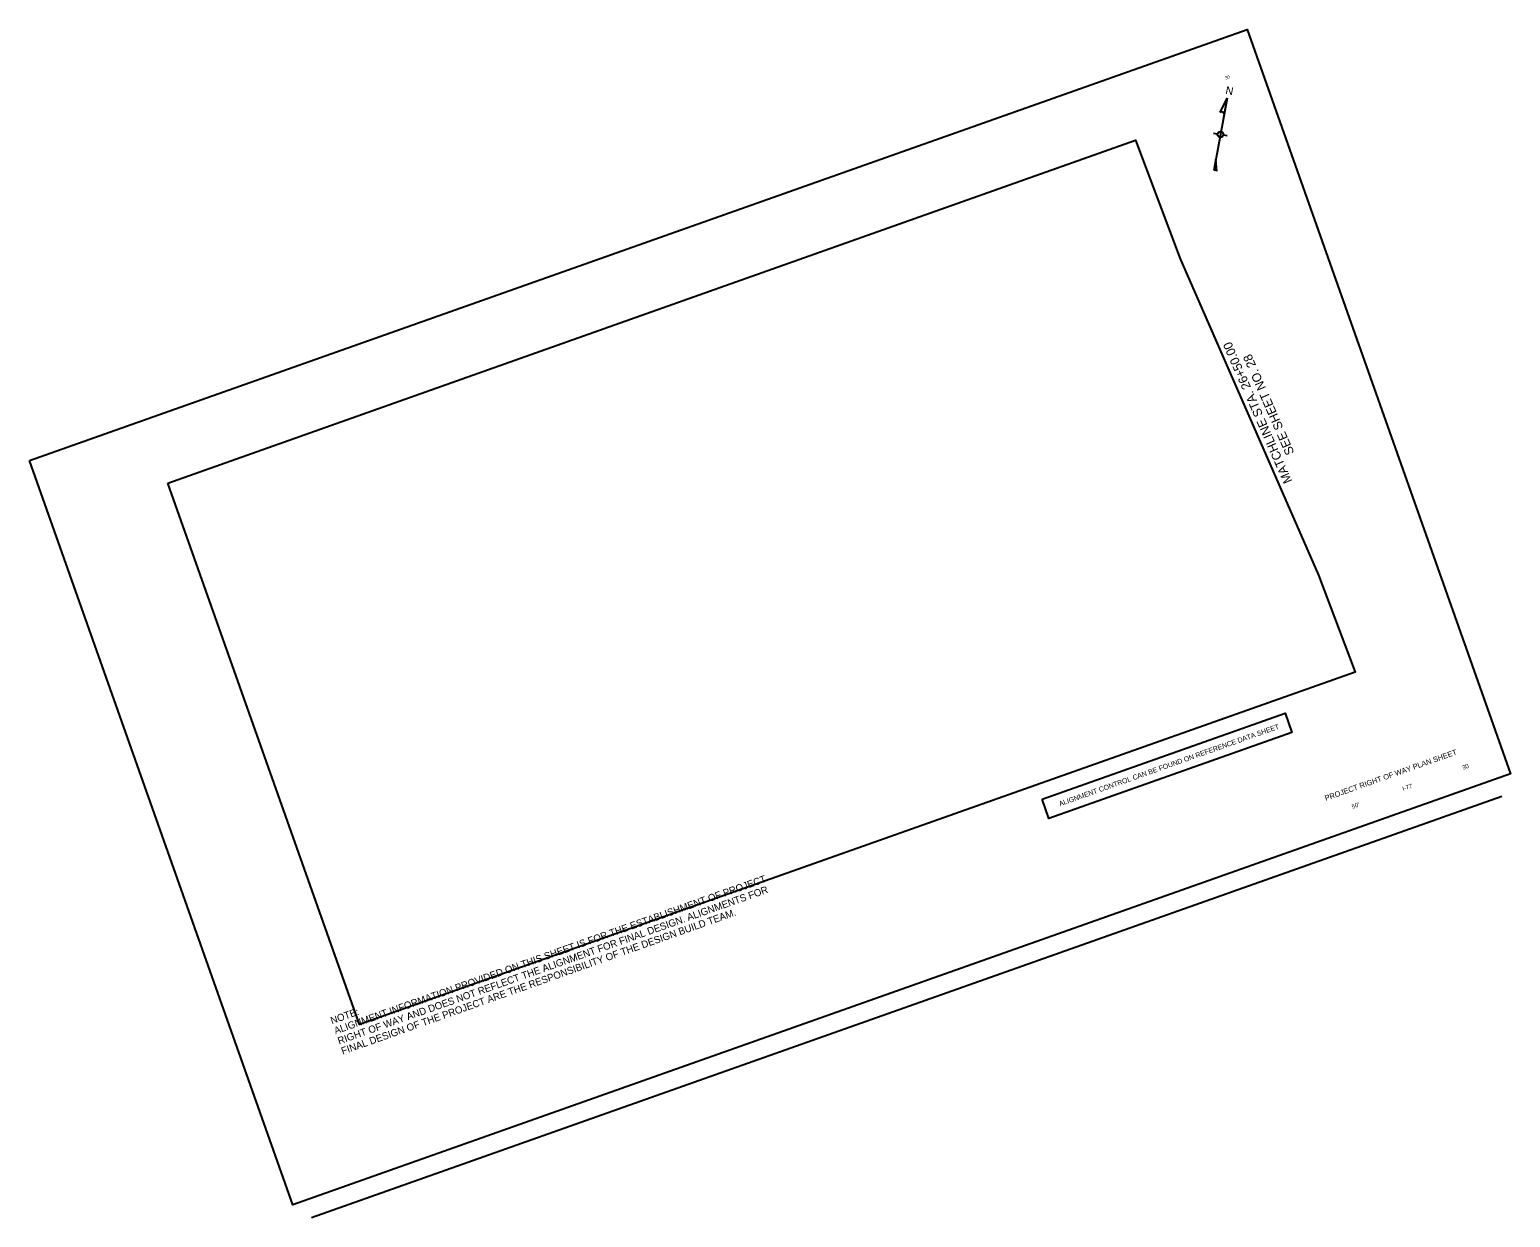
# Model space of a CAD drawing. Extents: x 2003337 to 2005401, y 1135705 to 1137360.
import ezdxf

# ---------------------------------------------------------------- set-up
doc = ezdxf.new("R2010")
doc.units = 0
for name, color, linetype in [('North Arrow', 7, 'Continuous'), ('RD_SHT_IplotShp', 7, 'Continuous'), ('RD_SHT_MatchLine', 7, 'Continuous'), ('RD_SHT_Misc1', 7, 'Continuous'), ('RD_SHT_ShtClip', 7, 'Continuous'), ('RD_SHT_TX', 7, 'Continuous')]:
    doc.layers.add(name, color=color, linetype=linetype)

msp = doc.modelspace()

# ---------------------------------------------------------------- linework, layer by layer
at = {"layer": 'North Arrow'}
for p, q in [((2005006.1, 1137264.4), (2004987.3, 1137163.9)), ((2004996.4, 1137244.8), (2005006.1, 1137264.4)), ((2005006.1, 1137264.4), (2005002, 1137242.6)), ((2004987.2, 1137215.9), (2004992.8, 1137214.9)), ((2005000.7, 1137213.4), (2005006.3, 1137212.4)), ((2004990.2, 1137179.5), (2004987.3, 1137163.9)), ((2004991.8, 1137162.8), (2004990.2, 1137179.5))]:
    msp.add_line(p, q, dxfattribs=at)
msp.add_circle((2004996.7, 1137214.2), 4.02, dxfattribs=at)
for centre, radius, start, end in [((2004998.5, 1137241.9), 3.59, 11.8077, 125.5757), ((2004989, 1137161.1), 3.3, 32.7767, 119.9977)]:
    msp.add_arc(centre, radius, start, end, dxfattribs=at)
at = {"layer": 'RD_SHT_IplotShp'}
msp.add_lwpolyline([(2003337, 1136759.8), (2005034, 1137360.1), (2005400.8, 1136323.1), (2003703.9, 1135722.8)], close=True, dxfattribs=at)
at = {"layer": 'RD_SHT_MatchLine'}
msp.add_line((2004940.5, 1137040.7), (2005133.6, 1136600.2), dxfattribs=at)
at = {"layer": 'RD_SHT_ShtClip'}
msp.add_lwpolyline([(2003529.8, 1136728.4), (2004878.4, 1137206.1), (2004940.5, 1137040.7), (2005133.6, 1136600.2), (2005184.4, 1136465.1), (2003796.6, 1135974.2)], close=True, dxfattribs=at)
at = {"layer": 'RD_SHT_TX'}
msp.add_line((2003729.8, 1135705.4), (2005389, 1136292.4), dxfattribs=at)
msp.add_lwpolyline([(2004748.3, 1136288.1), (2005086.9, 1136407.9), (2005096.3, 1136381.1), (2004757.7, 1136261.3)], close=True, dxfattribs=at)

# ---------------------------------------------------------------- texts
at = {"layer": 'North Arrow'}
msp.add_text('N', height=11.1, rotation=349.437, dxfattribs=at).set_placement((2005003.1, 1137270.6))
at = {"layer": 'RD_SHT_MatchLine'}
for s, p in [('MATCHLINE STA. 26+50.00', (2005096.9, 1136731.1)), ('SEE SHEET NO. 28', (2005100, 1136770.7))]:
    msp.add_text(s, height=12.5, rotation=113.6727, dxfattribs=at).set_placement(p)
at = {"layer": 'RD_SHT_Misc1'}
for s, p in [('ALIGNMENT INFORMATION PROVIDED ON THIS SHEET IS FOR THE ESTABLISHMENT OF PROJECT', (2003763.4, 1135960.3)), ('RIGHT OF WAY AND DOES NOT REFLECT THE ALIGNMENT FOR FINAL DESIGN. ALIGNMENTS FOR', (2003768.4, 1135946.1)), ('FINAL DESIGN OF THE PROJECT ARE THE RESPONSIBILITY OF THE DESIGN BUILD TEAM.', (2003773.4, 1135932)), ('NOTE:', (2003758.4, 1135974.4))]:
    msp.add_text(s, height=10, rotation=19.4825, dxfattribs=at).set_placement(p)
at = {"layer": 'RD_SHT_TX'}
for s, height, rotation, p in [('30', 4.5, 19.4825, (2005003.9, 1137290.1)), ('ALIGNMENT CONTROL CAN BE FOUND ON REFERENCE DATA SHEET', 7, 19.482, (2004772.9, 1136278)), ('PROJECT RIGHT OF WAY PLAN SHEET', 7.5, 19.4825, (2005143.7, 1136285.6)), ('30', 6, 19.4825, (2005334.8, 1136328.9)), ('I-77', 6, 19.4825, (2005251.5, 1136299.4)), ("50'", 6, 19.4825, (2005180.9, 1136274.5))]:
    msp.add_text(s, height=height, rotation=rotation, dxfattribs=at).set_placement(p)

doc.saveas('drawing.dxf')
